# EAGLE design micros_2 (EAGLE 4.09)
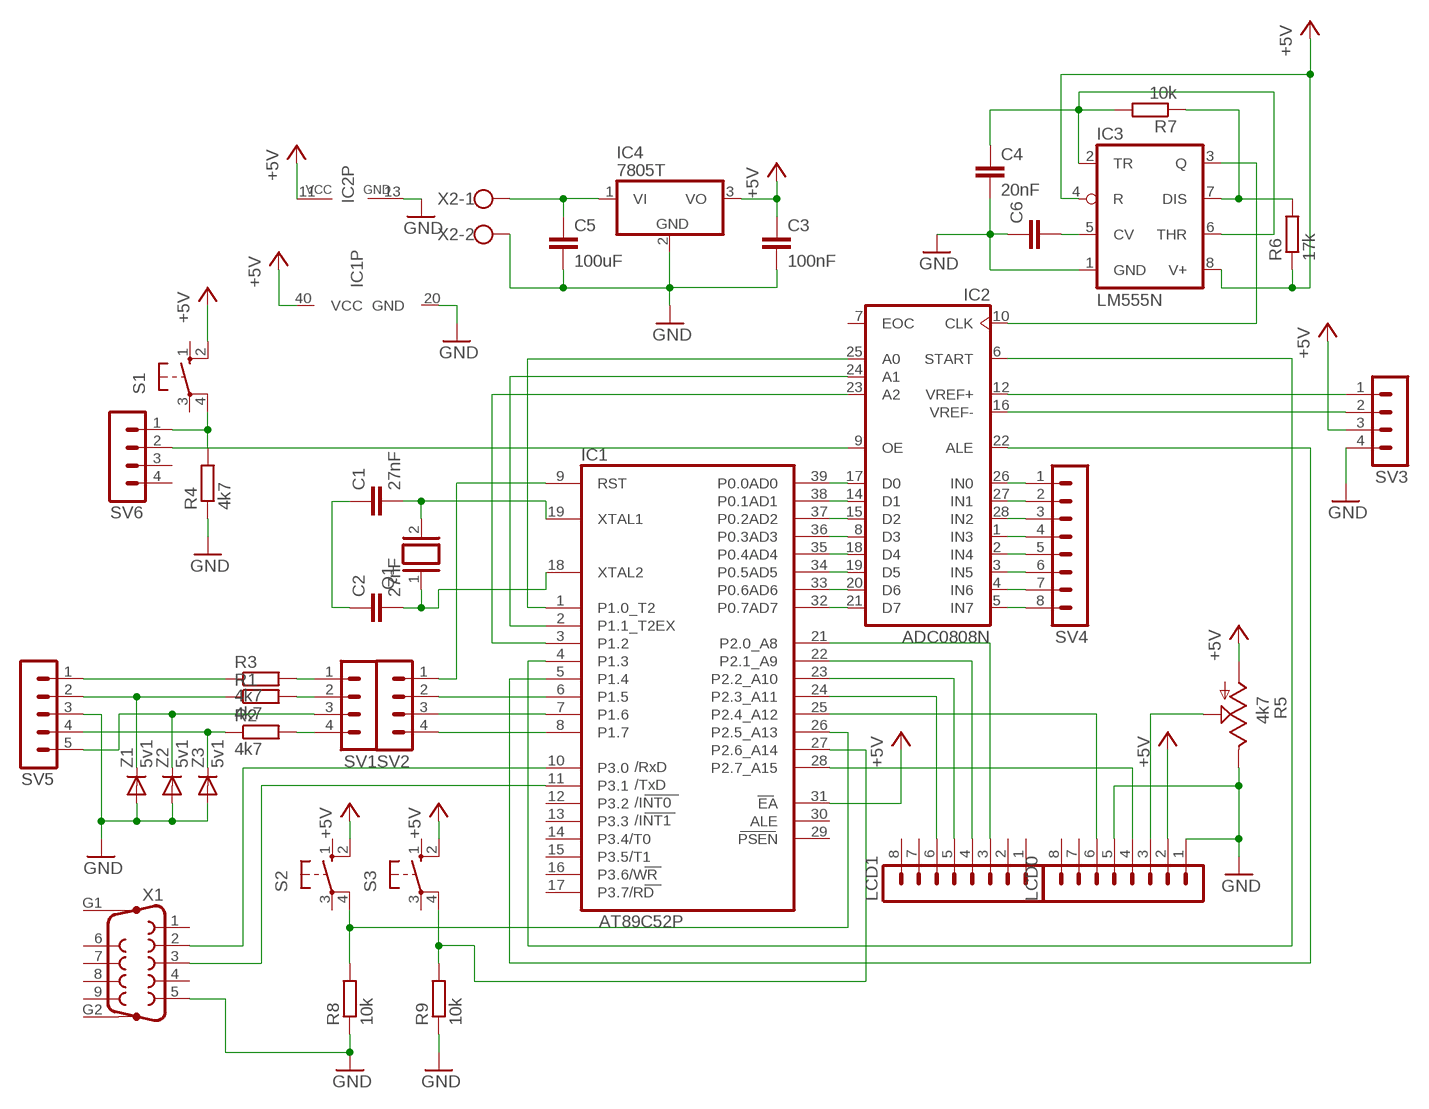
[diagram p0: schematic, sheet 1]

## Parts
C1  27nF  C-EU050-024X044  [C050-024X044]
C2  27nF  C-EU050-024X044  [C050-024X044]
C3  100nF  C-EU050-024X044  [C050-024X044]
C4  20nF  C-EU050-024X044  [C050-024X044]
C5  100uF  C-EU050-024X044  [C050-024X044]
C6  C-EU050-024X044  [C050-024X044]
IC1  AT89C52P  [DIL40]
IC2  ADC0808N  [DIL28-6]
IC3  LM555N  [DIL08]
IC4  7805T  [TO220H]
LCD0  MA08-1  [MA08-1]
LCD1  MA08-1  [MA08-1]
Q1  XTAL  [Q]
R1  4k7  R-EU_0204/7  [0204/7]
R2  4k7  R-EU_0204/7  [0204/7]
R3  4k7  R-EU_0204/7  [0204/7]
R4  4k7  R-EU_0204/7  [0204/7]
R5  4k7  TRIM_US-PT10  [PT-10]
R6  17k  R-EU_0204/7  [0204/7]
R7  10k  R-EU_0204/7  [0204/7]
R8  10k  R-EU_0204/7  [0204/7]
R9  10k  R-EU_0204/7  [0204/7]
S1  10-XX  [B3F-10XX]
S2  10-XX  [B3F-10XX]
S3  10-XX  [B3F-10XX]
SV1  MA04-1  [MA04-1]
SV2  MA04-1  [MA04-1]
SV3  MA04-1  [MA04-1]
SV4  MA08-1  [MA08-1]
SV5  MA05-1  [MA05-1]
SV6  MA04-1  [MA04-1]
X1  F09HP  [F09HP]
X2  AK500/2  [AK500/2]
Z1  5v1  DIODE-D-5  [D-5]
Z2  5v1  DIODE-D-5  [D-5]
Z3  5v1  DIODE-D-5  [D-5]

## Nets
+5V: C3.1 IC1.31(EA) IC1.40(VCC) IC2.11(VCC) IC3.4(R) IC3.8(V+) IC4.3(VO) LCD0.2 R5.A R6.1 S1.2(S1) S2.2(S1) S3.2(S1) SV3.3
GND: C1.1 C2.1 C3.2 C4.2 C5.2 C6.1 IC1.20(GND) IC2.13(GND) IC3.1(GND) IC4.2(GND) LCD0.1 LCD0.5 R4.1 R5.E R8.1 R9.1 SV3.4 SV5.3 X1.5 X2.2 Z1.A Z2.A Z3.A
N$1: SV1.3 SV5.5 Z2.C
N$2: IC1.10(P3.0) X1.2
N$3: C2.2 IC1.18(XTAL2) Q1.1
N$4: C1.2 IC1.19(XTAL1) Q1.2
N$5: IC1.7(P1.6) SV2.3
N$6: IC1.1(P1.0_T2) IC2.25(A0)
N$7: C6.2 IC3.5(CV)
N$8: R2.1 SV5.4 Z3.C
N$9: R2.2 SV1.4
N$10: IC1.11(P3.1) X1.3
N$11: IC1.2(P1.1_T2EX) IC2.24(A1)
N$12: R3.2 SV1.1
N$13: IC1.9(RST) SV2.1
N$14: IC1.24(P2.3_A11) LCD1.6
N$15: IC1.8(P1.7) SV2.4
N$16: R1.2 SV1.2
N$17: IC1.23(P2.2_A10) LCD1.5
N$18: IC1.22(P2.1_A9) LCD1.4
N$19: IC1.21(P2.0_A8) LCD1.3
N$20: LCD0.3 R5.S
N$21: IC2.26(IN0) SV4.1
N$22: IC2.27(IN1) SV4.2
N$23: IC2.28(IN2) SV4.3
N$24: IC2.1(IN3) SV4.4
N$25: IC1.25(P2.4_A12) LCD0.6
N$26: IC1.28(P2.7_A15) LCD0.4
N$27: IC1.36(P0.3AD3) IC2.8(D3)
N$28: IC1.38(P0.1AD1) IC2.14(D1)
N$29: IC1.37(P0.2AD2) IC2.15(D2)
N$30: IC1.39(P0.0AD0) IC2.17(D0)
N$31: IC1.35(P0.4AD4) IC2.18(D4)
N$32: IC1.34(P0.5AD5) IC2.19(D5)
N$33: IC1.33(P0.6AD6) IC2.20(D6)
N$34: IC1.32(P0.7AD7) IC2.21(D7)
N$35: IC2.2(IN4) SV4.5
N$36: IC2.3(IN5) SV4.6
N$37: IC2.4(IN6) SV4.7
N$38: IC2.5(IN7) SV4.8
N$39: R3.1 SV5.1
N$40: IC2.10(CLK) IC3.3(Q)
N$41: IC3.7(DIS) R6.2 R7.1
N$42: R1.1 SV5.2 Z1.C
N$43: C4.1 IC3.2(TR) IC3.6(THR) R7.2
N$44: IC1.3(P1.2) IC2.23(A2)
N$45: IC1.4(P1.3) IC2.6(START)
N$46: C5.1 IC4.1(VI) X2.1
N$47: IC1.5(P1.4) IC2.22(ALE)
N$48: IC2.12(VREF+) SV3.1
N$49: IC2.16(VREF-) SV3.2
N$50: R4.2 S1.4(P1) SV6.1
N$51: IC2.9(OE) SV6.2
N$52: IC1.26(P2.5_A13) R8.2 S2.4(P1)
N$53: IC1.6(P1.5) SV2.2
N$56: IC1.27(P2.6_A14) R9.2 S3.4(P1)
Unconnected: IC1.12(P3.2) IC1.13(P3.3) IC1.14(P3.4/T0) IC1.15(P3.5/T1) IC1.16(P3.6/WR) IC1.17(P3.7/RD) IC1.29(PSEN) IC1.30(ALE) IC2.7(EOC) LCD0.7 LCD0.8 LCD1.1 LCD1.2 LCD1.7 LCD1.8 S1.1(S) S1.3(P) S2.1(S) S2.3(P) S3.1(S) S3.3(P) SV6.3 SV6.4 X1.1 X1.4 X1.6 X1.7 X1.8 X1.9 X1.G1 X1.G2

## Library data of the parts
C1-C6 = rcl:C-EU: CAPACITOR, European symbol
IC1 = atmel:AT89C52P: MICROCONTROLLER 8 Kbytes FLASH
IC2 = linear:ADC0808: 8-bit A/D CONVERTER with 8-channel multiplexer
IC3 = linear:*555: TIMER
IC4 = linear:78*: Positive VOLTAGE REGULATOR
LCD0 LCD1 SV4 = con-lstb:MA08-1: PIN HEADER
Q1 = special:XTAL: CRYSTAL
R1-R4 R6-R9 = rcl:R-EU_: RESISTOR, European symbol
R5 = pot:TRIM_US-: POTENTIOMETER
S1-S3 = switch-omron:10-XX: OMRON SWITCH
SV1-SV3 SV6 = con-lstb:MA04-1: PIN HEADER
SV5 = con-lstb:MA05-1: PIN HEADER
X1 = con-subd:F09HP: SUB-D
X2 = con-ptr500:AK500/2: CONNECTOR
Z1-Z3 = diode:DIODE-: DIODE

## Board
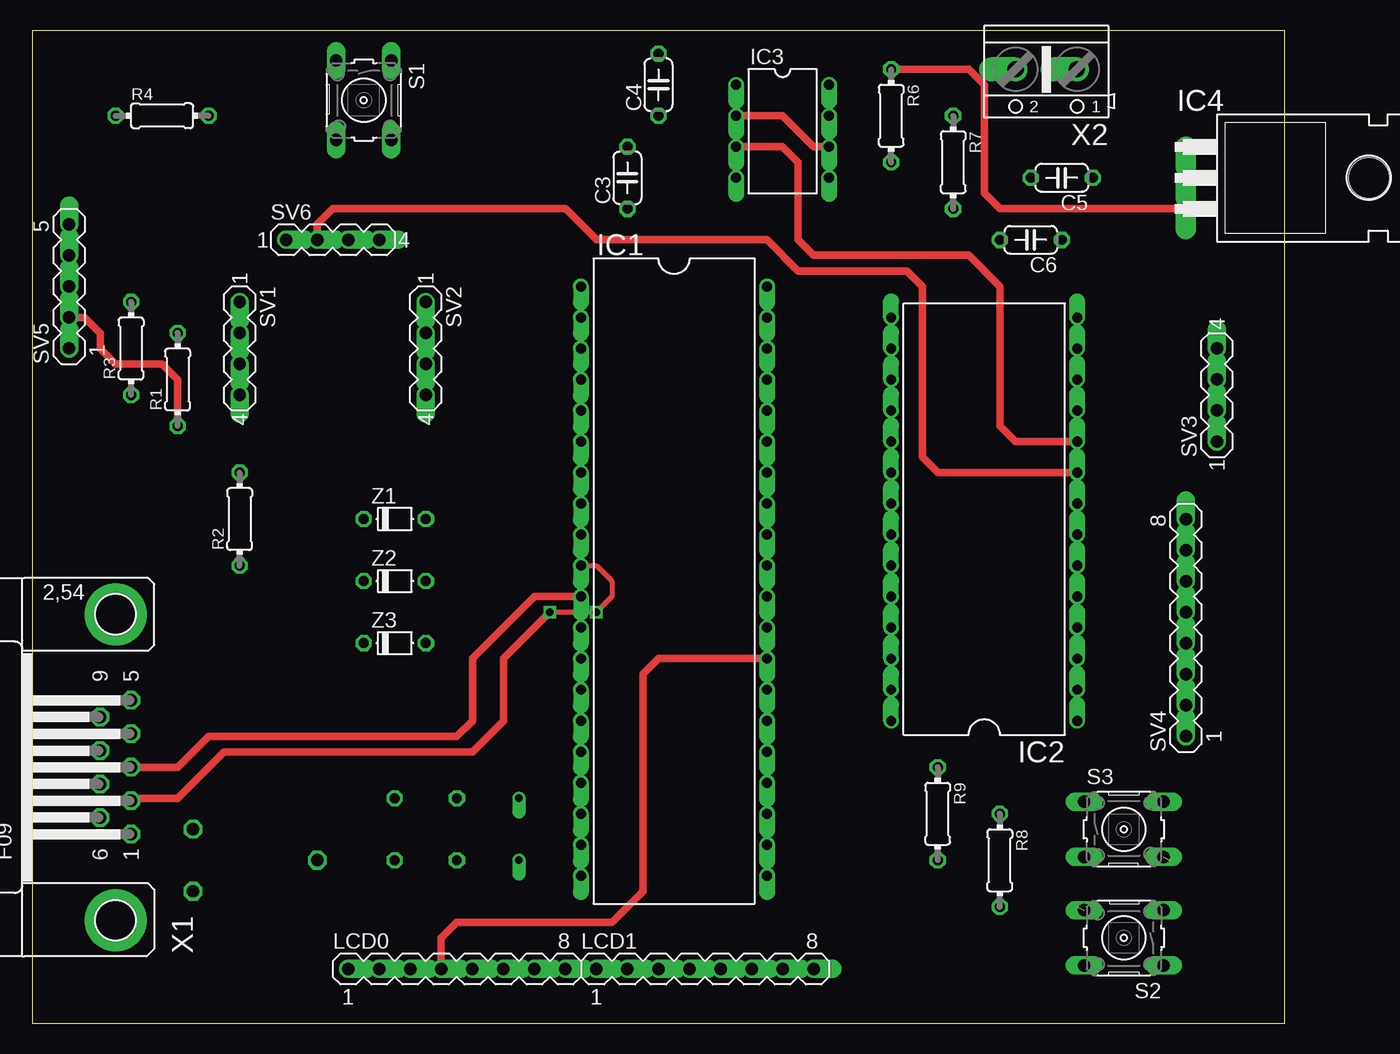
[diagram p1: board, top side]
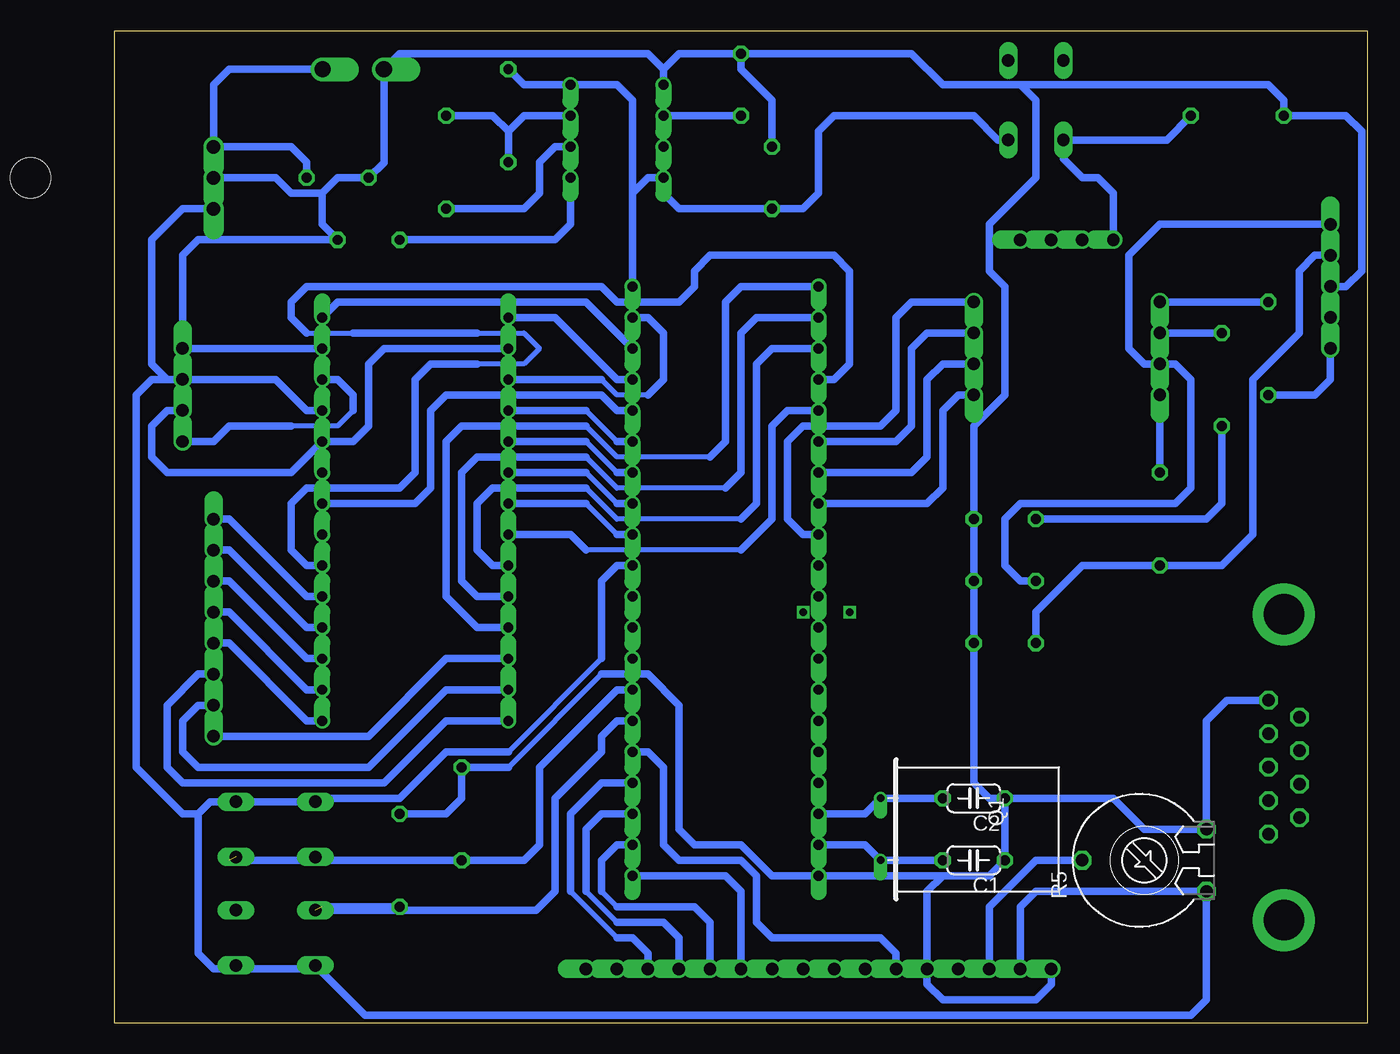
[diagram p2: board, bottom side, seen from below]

Size 102.54 x 81.27 mm. Coordinates in mm from the lower left corner, seen from the top.
Outline: 0,0 102.54,0 102.54,81.27 0,81.27 0,0
Copper layers used: Top, Bottom

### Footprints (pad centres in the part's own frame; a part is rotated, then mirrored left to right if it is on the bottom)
C050-024X044 = drill 0.813 octagon: 1 -2.54,0; 2 2.54,0
DIL40 = drill 0.813 offset: 1 -24.13,-7.62; 2 -21.59,-7.62; 3 -19.05,-7.62; 4 -16.51,-7.62; 5 -13.97,-7.62; 6 -11.43,-7.62; 7 -8.89,-7.62; 8 -6.35,-7.62; 9 -3.81,-7.62; 10 -1.27,-7.62; 11 1.27,-7.62; 12 3.81,-7.62; 13 6.35,-7.62; 14 8.89,-7.62; 15 11.43,-7.62; 16 13.97,-7.62; 17 16.51,-7.62; 18 19.05,-7.62; 19 21.59,-7.62; 20 24.13,-7.62; 21 24.13,7.62; 22 21.59,7.62; 23 19.05,7.62; 24 16.51,7.62; 25 13.97,7.62; 26 11.43,7.62; 27 8.89,7.62; 28 6.35,7.62; 29 3.81,7.62; 30 1.27,7.62; 31 -1.27,7.62; 32 -3.81,7.62; 33 -6.35,7.62; 34 -8.89,7.62; 35 -11.43,7.62; 36 -13.97,7.62; 37 -16.51,7.62; 38 -19.05,7.62; 39 -21.59,7.62; 40 -24.13,7.62
DIL28-6 = drill 0.813 offset: 1 -16.51,-7.62; 2 -13.97,-7.62; 3 -11.43,-7.62; 4 -8.89,-7.62; 5 -6.35,-7.62; 6 -3.81,-7.62; 7 -1.27,-7.62; 8 1.27,-7.62; 9 3.81,-7.62; 10 6.35,-7.62; 11 8.89,-7.62; 12 11.43,-7.62; 13 13.97,-7.62; 14 16.51,-7.62; 15 16.51,7.62; 16 13.97,7.62; 17 11.43,7.62; 18 8.89,7.62; 19 6.35,7.62; 20 3.81,7.62; 21 1.27,7.62; 22 -1.27,7.62; 23 -3.81,7.62; 24 -6.35,7.62; 25 -8.89,7.62; 26 -11.43,7.62; 27 -13.97,7.62; 28 -16.51,7.62
DIL08 = drill 0.813 offset: 1 -3.81,-3.81; 2 -1.27,-3.81; 3 1.27,-3.81; 4 3.81,-3.81; 5 3.81,3.81; 6 1.27,3.81; 7 -1.27,3.81; 8 -3.81,3.81
TO220H = drill 1.118 offset: 1 -2.54,-10.16; 2 0,-10.16; 3 2.54,-10.16 | hole 3.302: 0,4.826
MA08-1 = drill 1.016 offset: 1 -8.89,0; 2 -6.35,0; 3 -3.81,0; 4 -1.27,0; 5 1.27,0; 6 3.81,0; 7 6.35,0; 8 8.89,0
Q = drill 0.61 offset: 1 -2.54,-7.62; 2 2.54,-7.62
0204/7 = drill 0.813 octagon: 1 -3.81,0; 2 3.81,0
PT-10 = drill 1.016 octagon: A -2.54,-5.08; E 2.54,-5.08; S 0,5.08
B3F-10XX = drill 1.016 long: 1 -3.251,2.261; 2 3.251,2.261; 3 -3.251,-2.261; 4 3.251,-2.261
MA04-1 = drill 1.016 offset: 1 -3.81,0; 2 -1.27,0; 3 1.27,0; 4 3.81,0
MA05-1 = drill 1.016 offset: 1 -5.08,0; 2 -2.54,0; 3 0,0; 4 2.54,0; 5 5.08,0
F09HP = drill 1.016 octagon: 1 -5.486,-1.27; 2 -2.743,-1.27; 3 0,-1.27; 4 2.743,-1.27; 5 5.486,-1.27; 6 -4.115,1.27; 7 -1.372,1.27; 8 1.372,1.27; 9 4.115,1.27 | drill 3.302 pad 5.08 round: G1 -12.522,0; G2 12.522,0
AK500/2 = drill 1.321 offset: 1 -2.515,0; 2 2.515,0
D-5 = drill 0.813 octagon: A 2.54,0; C -2.54,0

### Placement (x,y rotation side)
C1  32.22,13.33 180 bottom
C2  32.22,18.41 180 bottom
C3  48.73,69.21 90 top
C4  51.27,76.83 90 top
C5  84.29,69.21 180 top
C6  81.75,64.13 180 top
IC1  52.54,36.19 270 top
IC2  77.94,41.27 90 top
IC3  61.43,73.02 270 top
IC4  104.61,69.21 270 top
LCD0  34.76,4.44 0 top
LCD1  55.08,4.44 0 top
Q1  32.22,15.87 270 bottom
R1  11.9,52.7 90 top
R2  16.98,41.27 90 top
R3  8.09,55.24 90 top
R4  10.63,74.29 0 top
R5  18.25,13.33 90 bottom
R6  70.32,74.29 270 top
R7  75.4,70.48 270 top
R8  79.21,13.33 270 top
R9  74.13,17.14 270 top
S1  27.14,75.56 270 top
S2  89.37,6.98 180 top
S3  89.37,15.87 0 top
SV1  16.98,55.24 270 top
SV2  32.22,55.24 270 top
SV3  96.99,51.43 90 top
SV4  94.45,32.38 90 top
SV5  3.01,60.32 90 top
SV6  24.6,64.13 0 top
X1  6.82,20.95 90 top
X2  83.02,78.1 180 top
Z1  29.68,41.27 0 top
Z2  29.68,36.19 0 top
Z3  29.68,31.11 0 top

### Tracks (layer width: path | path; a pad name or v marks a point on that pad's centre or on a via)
+5V
  Top 0.61: IC4.3 79.21,66.67 77.94,67.94 77.94,76.83 76.67,78.1 R6.1
  Bottom 0.406: 70.32,22.22 62.7,29.84
  Bottom 0.61: S1.2 30.24,72.31 32.22,74.29 43.65,74.29 44.92,73.02 44.92,67.94 46.19,66.67 C3.1 56.35,66.67 57.62,67.94 IC3.4 58.89,69.21 60.16,67.94 | R6.1 69.05,76.83 IC3.8 61.43,76.83 60.16,75.56 60.16,67.94 | IC4.3 96.99,66.67 99.53,64.13 99.53,53.97 98.26,52.7 | 95.72,17.14 94.73,18.13 S3.2 85.84,18.13 85.56,18.41 79.21,18.41 75.4,22.22 70.32,22.22 | 95.72,17.14 95.72,5.71 94.45,4.44 86.4,4.44 S2.2 82.03,0.63 14.44,0.63 13.17,1.9 R5.A 27.14,10.79 28.41,9.52 LCD0.2 | 98.26,52.7 SV3.3 89.37,52.7 86.83,50.16 IC2.11 | 60.16,67.94 IC1.40 | 98.26,52.7 99.53,52.7 100.8,51.43 100.8,20.95 96.99,17.14 95.72,17.14 | 62.7,29.84 62.7,36.19 61.43,37.46 IC1.31
GND
  Bottom 0.406: 62.7,28.57 70.32,20.95
  Bottom 0.61: C4.2 56.35,79.37 57.62,78.1 | 57.62,78.1 IC3.1 | 85.56,67.94 84.29,69.21 C5.2 80.5,70.46 X2.2 80.48,78.1 79.21,79.37 58.89,79.37 57.62,78.1 | IC4.2 89.37,69.21 88.1,67.94 85.56,67.94 | 85.56,67.94 85.56,65.4 C6.1 95.72,64.13 96.99,62.86 SV3.4 IC2.13 | 28.41,76.83 8.09,76.83 6.82,75.56 R4.1 1.74,74.29 0.47,73.02 0.47,61.59 1.74,60.32 SV5.3 | 28.41,76.83 34.76,76.83 37.3,79.37 C4.2 | C2.1 30.95,18.41 32.22,19.68 Z3.A Z2.A Z1.A 32.22,48.89 29.68,51.43 29.68,60.32 30.95,61.59 30.95,65.4 27.14,69.21 27.14,75.56 28.41,76.83 | LCD0.1 25.87,3.17 27.14,1.9 34.76,1.9 36.03,3.17 LCD0.5 36.03,10.79 34.76,12.06 | 34.76,12.06 30.95,12.06 C1.1 C2.1 | 34.76,12.06 IC1.20 48.73,12.06 51.27,14.6 55.08,14.6 56.35,15.87 56.35,26.03 58.89,28.57 62.7,28.57 | C3.2 48.73,75.56 51.27,78.1 C4.2 | X1.5 11.49,26.44 13.17,24.76 R5.E 18.25,15.87 20.79,18.41 C2.1 | 70.32,20.95 R9.1 74.13,18.41 75.4,17.14 R8.1
N$1
  Bottom 0.61: Z2.C 28.41,36.19 29.68,37.46 29.68,41.27 28.41,42.54 15.71,42.54 14.44,43.81 14.44,52.7 15.71,53.97 SV1.3 18.25,53.97 19.52,55.24 19.52,62.86 16.98,65.4 SV5.5
N$2  (via drill 0.61)
  Top 0.406: IC1.10 46.19,37.46 47.46,36.19 47.46,34.92 v46.19,33.65 v42.38,33.65
  Top 0.61: v42.38,33.65 38.57,29.84 38.57,24.76 36.03,22.22 15.71,22.22 11.9,18.41 8.09,18.41 X1.2
N$3
  Bottom 0.61: C2.2 Q1.1 41.11,17.14 IC1.18
N$4
  Bottom 0.61: IC1.19 41.11,14.6 Q1.2 C1.2
N$5
  Bottom 0.61: SV2.3 34.76,53.97 36.03,52.7 36.03,46.35 37.3,45.08 IC1.7
N$6
  Bottom 0.406: 63.97,48.89 61.43,46.35 53.81,46.35
  Bottom 0.61: IC2.25 72.86,32.38 75.4,34.92 75.4,47.62 74.13,48.89 63.97,48.89 | 53.81,46.35 52.54,47.62 52.54,59.05 51.27,60.32 IC1.1
N$7
  Bottom 0.61: C6.2 66.51,64.13 65.24,65.4 IC3.5
N$8
  Bottom 0.61: SV5.4 4.28,62.86 5.55,61.59 5.55,56.51 9.36,52.7 9.36,40 11.9,37.46 R2.1 23.33,37.46 27.14,33.65 Z3.C
N$9
  Bottom 0.61: R2.2 SV1.4
N$10
  Top 0.61: IC1.11 41.11,34.92 36.03,29.84 36.03,24.76 34.76,23.49 14.44,23.49 11.9,20.95 X1.3
N$11
  Bottom 0.406: 63.97,46.35 61.43,43.81 52.54,43.81
  Bottom 0.61: IC2.24 72.86,34.92 74.13,36.19 74.13,45.08 72.86,46.35 63.97,46.35 | 52.54,43.81 51.27,45.08 51.27,56.51 50,57.78 IC1.2
N$12
  Bottom 0.61: R3.2 SV1.1
N$13
  Bottom 0.61: IC1.9 46.19,40 47.46,41.27 47.46,47.62 46.19,48.89 39.84,48.89 38.57,50.16 38.57,57.78 37.3,59.05 SV2.1
N$14
  Bottom 0.406: 61.43,6.98 65.24,10.79
  Bottom 0.61: IC1.24 62.7,19.68 65.24,17.14 65.24,10.79 | 61.43,6.98 60.16,6.98 58.89,5.71 LCD1.6
N$15
  Bottom 0.61: SV2.4 33.49,51.43 34.76,50.16 34.76,43.81 36.03,42.54 IC1.8
N$16
  Bottom 0.61: R1.2 SV1.2
N$17
  Bottom 0.406: 61.43,8.25 63.97,10.79
  Bottom 0.61: IC1.23 62.7,17.14 63.97,15.87 63.97,10.79 | 61.43,8.25 57.62,8.25 56.35,6.98 LCD1.5
N$18
  Bottom 0.406: 61.43,9.52 62.7,10.79
  Bottom 0.61: IC1.22 61.43,14.6 62.7,13.33 62.7,10.79 | 61.43,9.52 55.08,9.52 53.81,8.25 LCD1.4
N$19
  Bottom 0.61: LCD1.3 51.27,10.79 52.54,12.06 IC1.21
N$20
  Bottom 0.61: R5.S 27.14,13.33 30.95,9.52 LCD0.3
N$21
  Bottom 0.61: IC2.26 75.4,29.84 81.75,23.49 SV4.1
N$22
  Bottom 0.61: IC2.27 75.4,27.3 81.75,20.95 95.72,20.95 96.99,22.22 96.99,24.76 95.72,26.03 SV4.2
N$23
  Bottom 0.61: IC2.28 75.4,24.76 80.48,19.68 96.99,19.68 98.26,20.95 98.26,26.03 95.72,28.57 SV4.3
N$24
  Bottom 0.61: IC2.1 86.83,24.76 93.18,31.11 SV4.4
N$25
  Bottom 0.61: IC1.25 58.89,22.22 57.62,20.95 57.62,14.6 56.35,13.33 51.27,13.33 50,12.06 50,8.25 48.73,6.98 39.84,6.98 38.57,5.71 LCD0.6
N$26
  Top 0.61: IC1.28 51.27,29.84 50,28.57 50,10.79 47.46,8.25 34.76,8.25 33.49,6.98 LCD0.4
N$27
  Bottom 0.61: IC1.36 61.43,50.16 62.7,51.43 75.4,51.43 76.67,50.16 76.67,43.81 77.94,42.54 IC2.8
N$28
  Bottom 0.61: IC2.14 84.29,59.05 63.97,59.05 IC1.38
N$29
  Bottom 0.61: IC1.37 61.43,52.7 66.51,57.78 IC2.15
N$30
  Bottom 0.406: 58.89,51.43 61.43,51.43 62.7,52.7
  Bottom 0.61: 62.7,52.7 IC2.17 | 58.89,51.43 57.62,52.7 57.62,56.51 58.89,57.78 IC1.39
N$31
  Bottom 0.406: 61.43,47.62 63.97,50.16
  Bottom 0.61: IC1.35 61.43,47.62 | 63.97,50.16 IC2.18
N$32
  Bottom 0.406: 61.43,45.08 63.97,47.62
  Bottom 0.61: IC1.34 61.43,45.08 | 63.97,47.62 IC2.19
N$33
  Bottom 0.406: 61.43,42.54 63.97,45.08
  Bottom 0.61: IC1.33 61.43,42.54 | 63.97,45.08 IC2.20
N$34
  Bottom 0.406: 61.43,40 63.97,42.54
  Bottom 0.61: IC1.32 61.43,40 | 63.97,42.54 IC2.21
N$35
  Bottom 0.61: IC2.2 86.83,27.3 93.18,33.65 SV4.5
N$36
  Bottom 0.61: IC2.3 86.83,29.84 93.18,36.19 SV4.6
N$37
  Bottom 0.61: IC2.4 86.83,32.38 93.18,38.73 SV4.7
N$38
  Bottom 0.61: IC2.5 86.83,34.92 93.18,41.27 SV4.8
N$39
  Bottom 0.61: SV5.1 3.01,52.7 4.28,51.43 R3.1
N$40
  Top 0.61: IC3.3 61.43,71.75 62.7,70.48 62.7,64.13 63.97,62.86 76.67,62.86 79.21,60.32 79.21,48.89 80.48,47.62 IC2.10
N$41
  Bottom 0.61: IC3.7 69.05,74.29 70.32,73.02 | 70.32,73.02 R6.2 | R7.1 71.59,74.29 70.32,73.02
N$42
  Top 0.61: SV5.2 4.28,57.78 5.55,56.51 5.55,55.24 6.82,53.97 10.63,53.97 11.9,52.7 R1.1
  Bottom 0.61: Z1.C 13.17,41.27 11.9,42.54 R1.1
N$43
  Top 0.61: IC3.2 61.43,74.29 63.97,71.75 IC3.6
  Bottom 0.61: C4.1 IC3.2 | R7.2 69.05,66.67 67.78,67.94 67.78,70.48 66.51,71.75 IC3.6
N$44
  Bottom 0.406: 63.97,43.81 61.43,41.27 51.27,41.27
  Bottom 0.61: IC2.23 71.59,37.46 72.86,38.73 72.86,42.54 71.59,43.81 63.97,43.81 | 51.27,41.27 50,42.54 50,53.97 48.73,55.24 IC1.3
N$45
  Bottom 0.406: 72.86,53.97 69.05,53.97 67.78,55.24 69.05,56.51 72.86,56.51 | 86.83,56.51 83.02,56.51
  Bottom 0.61: IC2.6 86.83,37.46 88.1,38.73 88.1,42.54 86.83,43.81 79.21,43.81 77.94,45.08 77.94,52.7 76.67,53.97 72.86,53.97 | IC1.4 43.65,52.7 42.38,53.97 42.38,61.59 43.65,62.86 53.81,62.86 55.08,61.59 55.08,60.32 56.35,59.05 61.43,59.05 62.7,60.32 86.83,60.32 88.1,59.05 88.1,57.78 86.83,56.51 | 83.02,56.51 72.86,56.51
N$46
  Bottom 0.61: X2.1 93.18,78.1 94.45,76.83 IC4.1 88.1,71.75 86.83,70.48 C5.1
N$47
  Bottom 0.406: 51.27,38.73 63.97,38.73
  Bottom 0.61: 51.27,38.73 48.73,41.27 48.73,48.89 47.46,50.16 IC1.5 | IC2.22 65.24,40 63.97,38.73
N$48
  Bottom 0.406: 88.1,48.89 84.29,48.89 83.02,50.16
  Bottom 0.61: IC2.12 84.29,52.7 83.02,51.43 83.02,50.16 | SV3.1 94.45,47.62 93.18,48.89 88.1,48.89
N$49
  Bottom 0.61: SV3.2 98.26,50.16 99.53,48.89 99.53,46.35 98.26,45.08 88.1,45.08 85.56,47.62 83.02,47.62 81.75,48.89 81.75,53.97 80.48,55.24 IC2.16
N$50
  Bottom 0.61: R4.2 16.42,72.31 S1.4 24.88,70.76 23.33,69.21 22.06,69.21 20.79,67.94 SV6.1
N$51
  Top 0.61: SV6.2 23.33,65.4 24.6,66.67 43.65,66.67 46.19,64.13 60.16,64.13 62.7,61.59 71.59,61.59 72.86,60.32 72.86,46.35 74.13,45.08 IC2.9
N$52  (1 unrouted)
  Bottom 0.61: S2.4 68.06,9.24 66.51,10.79 66.51,18.41 62.7,22.22 62.7,23.49 61.43,24.76 IC1.26 | R8.2 85.56,9.52
N$53
  Bottom 0.61: SV2.2 36.03,56.51 37.3,55.24 37.3,48.89 38.57,47.62 IC1.6
N$56  (1 unrouted)
  Bottom 0.61: IC1.27 61.43,27.3 67.78,20.95 67.78,14.6 69.05,13.33 72.86,13.33 R9.2 93.18,13.33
